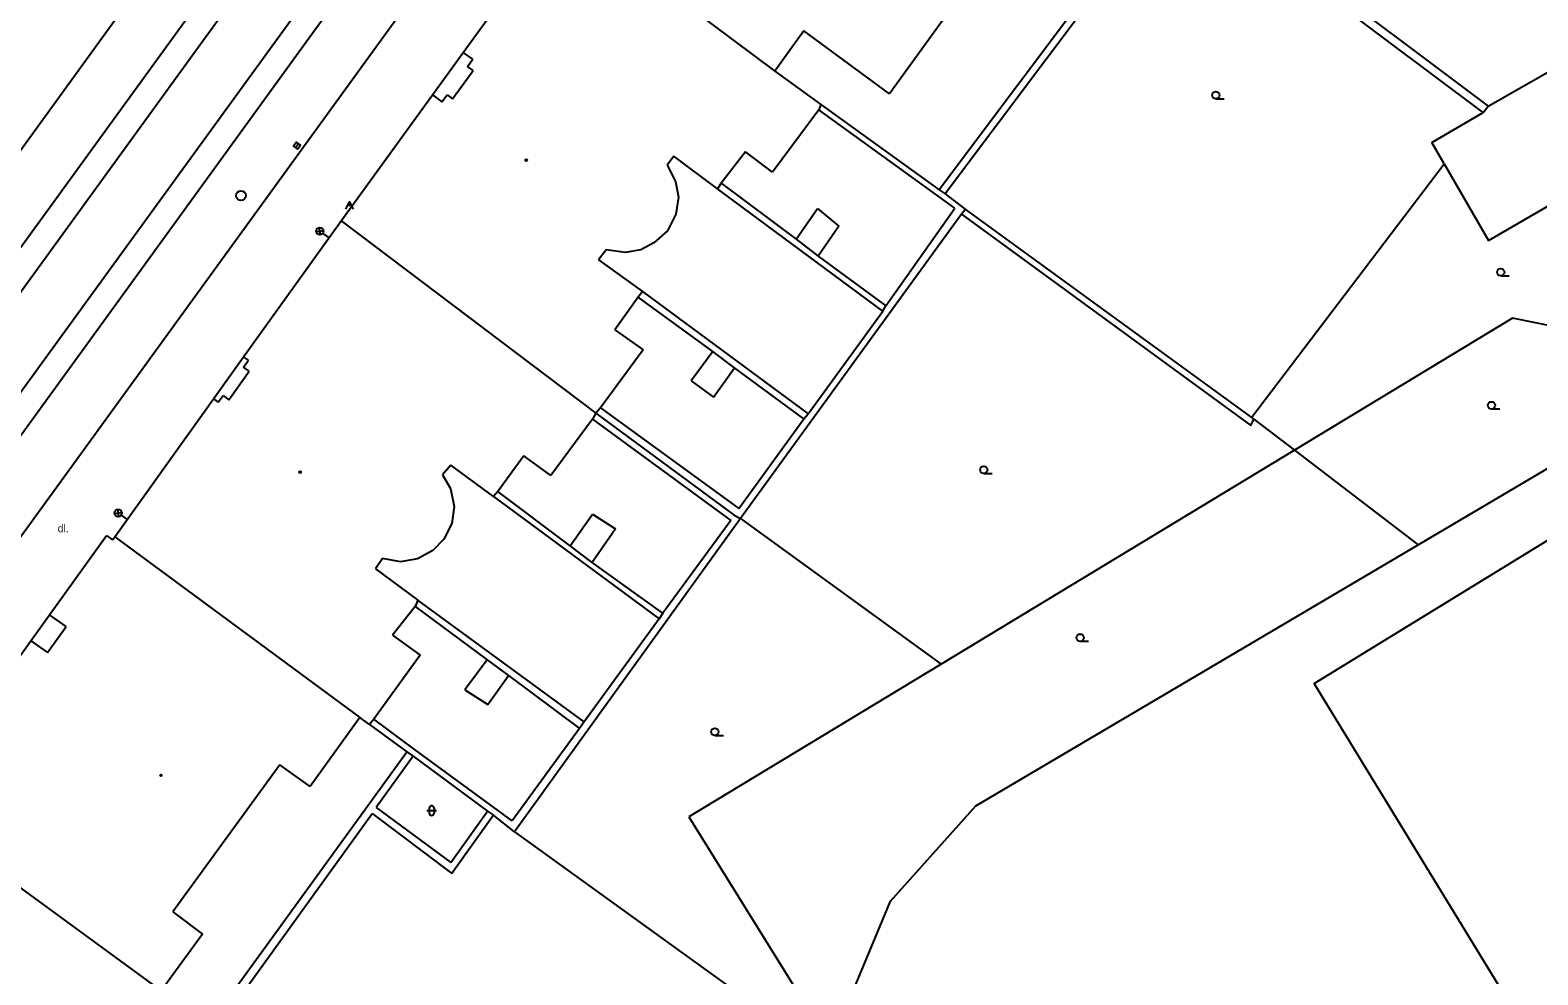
# Model space of a CAD drawing. Extents: x -599770 to -598493, y -1162076 to -1159209.
# Drawn here: x -598971.2 to -598893.6, y -1159496.2 to -1159447.5 of the extents above; entities that cross this region are included whole.
import ezdxf

# ---------------------------------------------------------------- set-up
doc = ezdxf.new("R2010")
doc.units = 0
doc.layers.add('Podklad', color=7, linetype='Continuous')

msp = doc.modelspace()

# ---------------------------------------------------------------- linework, layer by layer
at = {"layer": 'Podklad'}
for p, q in [((-598910.15, -1159451.067), (-598909.712, -1159451.067)), ((-598957.562, -1159453.582), (-598957.418, -1159453.378)), ((-598954.868, -1159456.55), (-598954.693, -1159456.55)), ((-598954.855, -1159456.525), (-598954.705, -1159456.525)), ((-598954.843, -1159456.5), (-598954.718, -1159456.5)), ((-598954.83, -1159456.475), (-598954.73, -1159456.475)), ((-598954.818, -1159456.45), (-598954.743, -1159456.45)), ((-598956.498, -1159457.915), (-598956.128, -1159457.858)), ((-598956.285, -1159458.072), (-598956.341, -1159457.701)), ((-598956.162, -1159457.998), (-598955.86, -1159458.22)), ((-598895.47, -1159460.188), (-598895.032, -1159460.188)), ((-598895.95, -1159467.047), (-598895.512, -1159467.047)), ((-598922.11, -1159470.367), (-598921.672, -1159470.367)), ((-598966.888, -1159472.435), (-598966.518, -1159472.378)), ((-598966.675, -1159472.592), (-598966.731, -1159472.221)), ((-598966.552, -1159472.518), (-598966.25, -1159472.74)), ((-598917.14, -1159479.017), (-598916.703, -1159479.017)), ((-598935.96, -1159483.867), (-598935.523, -1159483.867)), ((-598950.678, -1159487.613), (-598950.678, -1159487.863)), ((-598950.428, -1159487.613), (-598950.428, -1159487.863)), ((-598950.803, -1159487.738), (-598950.303, -1159487.738))]:
    msp.add_line(p, q, dxfattribs=at)
for points in [[(-598999.14, -1159498.8), (-598906.32, -1159370.83)], [(-598902.25, -1159370.53), (-598996.71, -1159500.56)], [(-599014.3, -1159517.46), (-599012.233, -1159514.605), (-599011.699, -1159513.868), (-599004.953, -1159504.571), (-599000.363, -1159498.212), (-598984.15, -1159475.82), (-598951.27, -1159430.52), (-598936.439, -1159410.106), (-598915.09, -1159380.72)], [(-598911.04, -1159383.64), (-598910.593, -1159383.963), (-598910.5, -1159384.03), (-598931.723, -1159413.266), (-598946.98, -1159434.283), (-598954.76, -1159445), (-598988.18, -1159491.09), (-598995.703, -1159501.492), (-599000.426, -1159508.024), (-599007.087, -1159517.234), (-599007.33, -1159517.57)], [(-598946.73, -1159419.22), (-599007.295, -1159502.784), (-599012.68, -1159510.15)], [(-598988.64, -1159496.91), (-598944.893, -1159436.625), (-598937.35, -1159426.23)], [(-598903.51, -1159427.9), (-598924.4, -1159455.75)], [(-598903.19, -1159428.13), (-598924.1, -1159455.97)], [(-598918.77, -1159439.48), (-598926.96, -1159450.81)], [(-598948.93, -1159448.68), (-598943.74, -1159441.53)], [(-598943.62, -1159441.61), (-598932.88, -1159449.64)], [(-598896.37, -1159451.78), (-598906.62, -1159444.1)], [(-598906.06, -1159443.97), (-598896.11, -1159451.44)], [(-598931.37, -1159447.56), (-598932.88, -1159449.64)], [(-598926.96, -1159450.81), (-598931.37, -1159447.56)], [(-598950.51, -1159450.86), (-598948.93, -1159448.68)], [(-598948.44, -1159449.03), (-598948.93, -1159448.68)], [(-598896.11, -1159451.44), (-598890.49, -1159448.24)], [(-598949.48, -1159451.06), (-598948.42, -1159449.61)], [(-598948.71, -1159449.4), (-598948.44, -1159449.03)], [(-598948.42, -1159449.61), (-598948.71, -1159449.4)], [(-598932.88, -1159449.64), (-598930.5, -1159451.36)], [(-598955.21, -1159457.35), (-598950.51, -1159450.86)], [(-598950.51, -1159450.86), (-598950.03, -1159451.22)], [(-598950.03, -1159451.22), (-598949.76, -1159450.86)], [(-598949.76, -1159450.86), (-598949.48, -1159451.06)], [(-598930.6, -1159451.64), (-598932.99, -1159454.84)], [(-598930.5, -1159451.36), (-598930.6, -1159451.64)], [(-598923.59, -1159456.7), (-598930.6, -1159451.64)], [(-598930.5, -1159451.36), (-598924.4, -1159455.75)], [(-598899.02, -1159453.32), (-598896.37, -1159451.78)], [(-598896.37, -1159451.78), (-598896.11, -1159451.44)], [(-598898.38, -1159454.42), (-598899.02, -1159453.32)], [(-598896.1, -1159458.37), (-598887.45, -1159453.35)], [(-598938.08, -1159454.02), (-598938.42, -1159454.49)], [(-598935.83, -1159455.7), (-598938.08, -1159454.02)], [(-598934.39, -1159453.8), (-598935.64, -1159455.41)], [(-598932.99, -1159454.84), (-598934.39, -1159453.8)], [(-598938.42, -1159454.49), (-598937.99, -1159455.32)], [(-598908.32, -1159467.48), (-598898.38, -1159454.42)], [(-598898.38, -1159454.42), (-598896.1, -1159458.37)], [(-598937.99, -1159455.32), (-598937.84, -1159456.14)], [(-598935.64, -1159455.41), (-598935.83, -1159455.7)], [(-598927.31, -1159462), (-598935.83, -1159455.7)], [(-598935.64, -1159455.41), (-598931.78, -1159458.3)], [(-598924.4, -1159455.75), (-598924.1, -1159455.97)], [(-598954.968, -1159456.75), (-598954.78, -1159456.375), (-598954.593, -1159456.75)], [(-598937.84, -1159456.14), (-598937.98, -1159457.01)], [(-598924.1, -1159455.97), (-598923.05, -1159456.77)], [(-598960.24, -1159464.36), (-598955.21, -1159457.35)], [(-598955.21, -1159457.35), (-598942.1, -1159467.27)], [(-598937.98, -1159457.01), (-598938.4, -1159457.87)], [(-598923.26, -1159457.01), (-598934.64, -1159472.69)], [(-598931.78, -1159458.3), (-598930.68, -1159456.72)], [(-598930.68, -1159456.72), (-598929.58, -1159457.62)], [(-598927.16, -1159461.74), (-598923.59, -1159456.7)], [(-598923.05, -1159456.77), (-598923.26, -1159457.01)], [(-598923.26, -1159457.01), (-598908.35, -1159467.9)], [(-598923.05, -1159456.77), (-598908.32, -1159467.48)], [(-598938.4, -1159457.87), (-598939.1, -1159458.49)], [(-598929.58, -1159457.62), (-598930.64, -1159459.18)], [(-598941.57, -1159458.84), (-598941.95, -1159459.36)], [(-598940.58, -1159458.99), (-598941.57, -1159458.84)], [(-598939.77, -1159458.85), (-598940.58, -1159458.99)], [(-598939.1, -1159458.49), (-598939.77, -1159458.85)], [(-598931.78, -1159458.3), (-598930.64, -1159459.18)], [(-598941.95, -1159459.36), (-598939.69, -1159460.99)], [(-598930.64, -1159459.18), (-598927.16, -1159461.74)], [(-598939.91, -1159461.28), (-598941.12, -1159462.97)], [(-598939.69, -1159460.99), (-598939.91, -1159461.28)], [(-598936.07, -1159464.08), (-598939.91, -1159461.28)], [(-598939.69, -1159460.99), (-598931.15, -1159467.29)], [(-598931.15, -1159467.29), (-598927.31, -1159462)], [(-598927.31, -1159462), (-598927.16, -1159461.74)], [(-598894.86, -1159462.36), (-598906.1, -1159469.17)], [(-598880.32, -1159465.33), (-598894.86, -1159462.36)], [(-598941.12, -1159462.97), (-598939.66, -1159464)], [(-598961.8, -1159466.53), (-598960.24, -1159464.36)], [(-598959.99, -1159464.53), (-598960.24, -1159464.36)], [(-598939.66, -1159464), (-598941.86, -1159466.99)], [(-598936.07, -1159464.08), (-598937.19, -1159465.6)], [(-598934.95, -1159464.92), (-598936.07, -1159464.08)], [(-598961.01, -1159466.57), (-598959.96, -1159465.1)], [(-598960.25, -1159464.89), (-598959.99, -1159464.53)], [(-598959.96, -1159465.1), (-598960.25, -1159464.89)], [(-598936.03, -1159466.43), (-598934.95, -1159464.92)], [(-598931.38, -1159467.56), (-598934.95, -1159464.92)], [(-598937.19, -1159465.6), (-598936.03, -1159466.43)], [(-598966.88, -1159473.63), (-598961.8, -1159466.53)], [(-598961.8, -1159466.53), (-598961.55, -1159466.7)], [(-598961.55, -1159466.7), (-598961.3, -1159466.36)], [(-598961.3, -1159466.36), (-598961.01, -1159466.57)], [(-598899.72, -1159474.05), (-598886.34, -1159466.15)], [(-598942.1, -1159467.27), (-598942.26, -1159467.57)], [(-598941.86, -1159466.99), (-598942.1, -1159467.27)], [(-598942.1, -1159467.27), (-598934.96, -1159472.51)], [(-598941.86, -1159466.99), (-598934.73, -1159472.18)], [(-598931.38, -1159467.56), (-598931.15, -1159467.29)], [(-598908.32, -1159467.48), (-598908.2, -1159467.57)], [(-598942.26, -1159467.57), (-598944.42, -1159470.47)], [(-598942.26, -1159467.57), (-598935.14, -1159472.79)], [(-598934.73, -1159472.18), (-598931.38, -1159467.56)], [(-598908.35, -1159467.9), (-598908.2, -1159467.57)], [(-598908.2, -1159467.57), (-598906.1, -1159469.17)], [(-598945.8, -1159469.46), (-598947.15, -1159471.29)], [(-598944.42, -1159470.47), (-598945.8, -1159469.46)], [(-598906.1, -1159469.17), (-598924.3, -1159480.19)], [(-598906.1, -1159469.17), (-598899.72, -1159474.05)], [(-598949.57, -1159469.94), (-598950, -1159470.44)], [(-598950, -1159470.44), (-598949.59, -1159471.15)], [(-598947.36, -1159471.56), (-598949.57, -1159469.94)], [(-598949.59, -1159471.15), (-598949.4, -1159472.07)], [(-598947.15, -1159471.29), (-598947.36, -1159471.56)], [(-598943.41, -1159474.09), (-598947.15, -1159471.29)], [(-598949.4, -1159472.07), (-598949.52, -1159472.95)], [(-598947.36, -1159471.56), (-598938.83, -1159477.85)], [(-598949.52, -1159472.95), (-598949.92, -1159473.76)], [(-598934.64, -1159472.69), (-598946.28, -1159488.84)], [(-598943.41, -1159474.09), (-598942.26, -1159472.46)], [(-598942.26, -1159472.46), (-598941.08, -1159473.23)], [(-598935.14, -1159472.79), (-598938.65, -1159477.56)], [(-598934.96, -1159472.51), (-598934.64, -1159472.69)], [(-598934.64, -1159472.69), (-598924.3, -1159480.19)], [(-598970.24, -1159477.65), (-598967.31, -1159473.57)], [(-598967.31, -1159473.57), (-598967, -1159473.79)], [(-598967, -1159473.79), (-598966.88, -1159473.63)], [(-598966.88, -1159473.63), (-598954.25, -1159482.95)], [(-598941.08, -1159473.23), (-598942.28, -1159474.95)], [(-598905.08, -1159481.19), (-598892.59, -1159473.53)], [(-598950.49, -1159474.33), (-598951.29, -1159474.77)], [(-598949.92, -1159473.76), (-598950.49, -1159474.33)], [(-598942.28, -1159474.95), (-598943.41, -1159474.09)], [(-598922.52, -1159487.5), (-598899.72, -1159474.05)], [(-598953.09, -1159474.75), (-598953.45, -1159475.29)], [(-598953.45, -1159475.29), (-598951.26, -1159476.89)], [(-598952.16, -1159474.92), (-598953.09, -1159474.75)], [(-598951.29, -1159474.77), (-598952.16, -1159474.92)], [(-598938.65, -1159477.56), (-598942.28, -1159474.95)], [(-598951.41, -1159477.23), (-598952.57, -1159478.7)], [(-598951.26, -1159476.89), (-598951.41, -1159477.23)], [(-598951.41, -1159477.23), (-598947.7, -1159479.97)], [(-598942.69, -1159483.17), (-598951.26, -1159476.89)], [(-598938.65, -1159477.56), (-598938.83, -1159477.85)], [(-598971.2, -1159478.99), (-598970.24, -1159477.65)], [(-598970.35, -1159479.6), (-598969.38, -1159478.26)], [(-598969.38, -1159478.26), (-598970.24, -1159477.65)], [(-598938.83, -1159477.85), (-598942.69, -1159483.17)], [(-598971.81, -1159479.84), (-598971.2, -1159478.99)], [(-598971.2, -1159478.99), (-598970.35, -1159479.6)], [(-598952.57, -1159478.7), (-598951.14, -1159479.73)], [(-598951.14, -1159479.73), (-598953.53, -1159483.02)], [(-598947.7, -1159479.97), (-598948.85, -1159481.52)], [(-598947.7, -1159479.97), (-598946.6, -1159480.78)], [(-598924.3, -1159480.19), (-598937.3, -1159488.06)], [(-598947.66, -1159482.27), (-598946.6, -1159480.78)], [(-598946.6, -1159480.78), (-598942.94, -1159483.5)], [(-598888.72, -1159507.97), (-598905.08, -1159481.19)], [(-598948.85, -1159481.52), (-598947.66, -1159482.27)], [(-598954.25, -1159482.95), (-598956.82, -1159486.5)], [(-598953.75, -1159483.31), (-598954.25, -1159482.95)], [(-598953.53, -1159483.02), (-598953.75, -1159483.31)], [(-598951.45, -1159484.58), (-598953.53, -1159483.02)], [(-598953.75, -1159483.31), (-598951.84, -1159484.71)], [(-598942.94, -1159483.5), (-598946.41, -1159488.26)], [(-598942.69, -1159483.17), (-598942.94, -1159483.5)], [(-598946.41, -1159488.26), (-598951.45, -1159484.58)], [(-598958.38, -1159485.38), (-598963.89, -1159492.96)], [(-598962.06, -1159498.83), (-598951.84, -1159484.71)], [(-598956.82, -1159486.5), (-598958.38, -1159485.38)], [(-598951.51, -1159484.93), (-598953.41, -1159487.58)], [(-598951.84, -1159484.71), (-598951.51, -1159484.93)], [(-598951.51, -1159484.93), (-598947.68, -1159487.76)], [(-598953.41, -1159487.58), (-598949.57, -1159490.41)], [(-598926.92, -1159492.41), (-598922.52, -1159487.5)], [(-598977.11, -1159487.8), (-598964.49, -1159497.03)], [(-598961.7, -1159499.11), (-598953.62, -1159487.88)], [(-598953.62, -1159487.88), (-598949.52, -1159490.98)], [(-598949.57, -1159490.41), (-598947.68, -1159487.76)], [(-598947.37, -1159487.97), (-598949.52, -1159490.98)], [(-598947.68, -1159487.76), (-598947.37, -1159487.97)], [(-598946.28, -1159488.84), (-598947.37, -1159487.97)], [(-598937.3, -1159488.06), (-598929.15, -1159501.19)], [(-598946.28, -1159488.84), (-598929.15, -1159501.19)], [(-598963.89, -1159492.96), (-598962.36, -1159494.11)], [(-598928.84, -1159497.02), (-598926.92, -1159492.41)], [(-598962.36, -1159494.11), (-598964.49, -1159497.03)]]:
    msp.add_lwpolyline(points, dxfattribs=at)
msp.add_lwpolyline([(-598957.46, -1159453.654), (-598957.316, -1159453.45), (-598957.52, -1159453.306), (-598957.664, -1159453.51)], close=True, dxfattribs=at)
for centre, radius in [((-598910.15, -1159450.88), 0.188), ((-598945.68, -1159454.23), 0.045), ((-598945.68, -1159454.23), 0.0199), ((-598960.38, -1159456.05), 0.25), ((-598956.313, -1159457.886), 0.188), ((-598895.47, -1159460), 0.188), ((-598895.95, -1159466.86), 0.188), ((-598957.33, -1159470.3), 0.045), ((-598957.33, -1159470.3), 0.0199), ((-598922.11, -1159470.18), 0.188), ((-598966.703, -1159472.407), 0.188), ((-598917.14, -1159478.83), 0.188), ((-598935.96, -1159483.68), 0.188), ((-598964.5, -1159485.92), 0.045), ((-598964.5, -1159485.92), 0.0199)]:
    msp.add_circle(centre, radius, dxfattribs=at)
for centre, start, end in [((-598950.553, -1159487.613), 0, 180), ((-598950.553, -1159487.863), 180, 0)]:
    msp.add_arc(centre, 0.125, start, end, dxfattribs=at)

# ---------------------------------------------------------------- texts
msp.add_text('dl.', height=0.4, dxfattribs=at).set_placement((-598969.82, -1159473.4))

doc.saveas('drawing.dxf')
